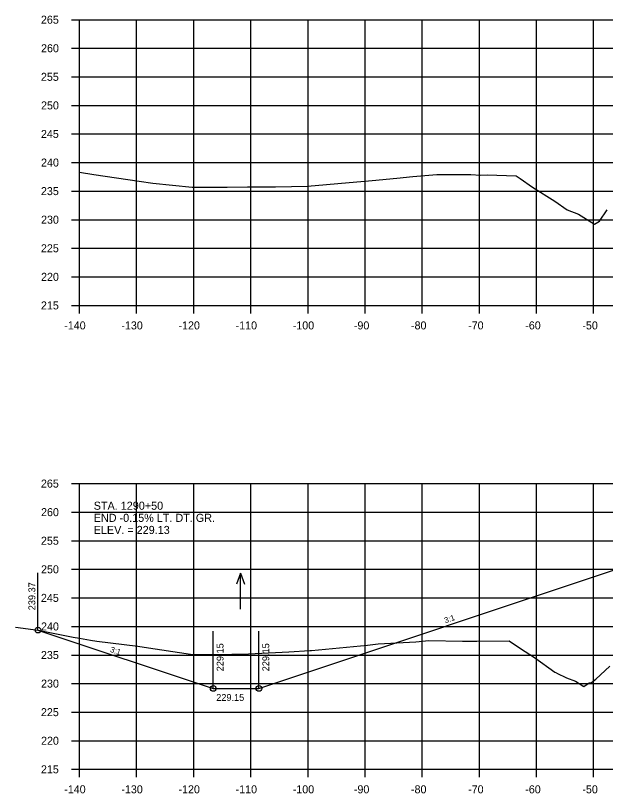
# Model space of a CAD drawing. Extents: x 1342547 to 1344156, y -1532351 to -1517216.
# Drawn here: x 1342551.7 to 1342654.9, y -1521241.8 to -1521105.7 of the extents above; entities that cross this region are included whole.
import ezdxf

# ---------------------------------------------------------------- set-up
doc = ezdxf.new("R2010")
doc.units = 0
for name, color, linetype in [('R_Axis', 7, 'Continuous'), ('R_Axis Annot', 7, 'Continuous'), ('R_Exist Surface', 7, 'Continuous'), ('R_Fin Surface', 7, 'Continuous'), ('R_Grid', 7, 'Continuous'), ('R_No Plot', 7, 'Continuous'), ('R_Water', 7, 'Continuous'), ('R_Water Annot', 7, 'Continuous'), ('R_Xsect Elev', 7, 'Continuous'), ('R_Xsect Slope', 7, 'Continuous')]:
    doc.layers.add(name, color=color, linetype=linetype)

msp = doc.modelspace()

# ---------------------------------------------------------------- linework, layer by layer
at = {"layer": 'R_Axis'}
for p, q in [((1342561.47, -1521106.39), (1342562.87, -1521106.39)), ((1342562.87, -1521156.39), (1342562.87, -1521106.39)), ((1342561.47, -1521111.39), (1342562.87, -1521111.39)), ((1342561.47, -1521116.39), (1342562.87, -1521116.39)), ((1342561.47, -1521121.39), (1342562.87, -1521121.39)), ((1342561.47, -1521126.39), (1342562.87, -1521126.39)), ((1342561.47, -1521131.39), (1342562.87, -1521131.39)), ((1342561.47, -1521136.39), (1342562.87, -1521136.39)), ((1342561.47, -1521141.39), (1342562.87, -1521141.39)), ((1342561.47, -1521146.39), (1342562.87, -1521146.39)), ((1342561.47, -1521151.39), (1342562.87, -1521151.39)), ((1342561.47, -1521156.39), (1342562.87, -1521156.39)), ((1342562.87, -1521156.39), (1342842.87, -1521156.39)), ((1342562.87, -1521157.79), (1342562.87, -1521156.39)), ((1342572.87, -1521157.79), (1342572.87, -1521156.39)), ((1342582.87, -1521157.79), (1342582.87, -1521156.39)), ((1342592.87, -1521157.79), (1342592.87, -1521156.39)), ((1342602.87, -1521157.79), (1342602.87, -1521156.39)), ((1342612.87, -1521157.79), (1342612.87, -1521156.39)), ((1342622.87, -1521157.79), (1342622.87, -1521156.39)), ((1342632.87, -1521157.79), (1342632.87, -1521156.39)), ((1342642.87, -1521157.79), (1342642.87, -1521156.39)), ((1342652.87, -1521157.79), (1342652.87, -1521156.39)), ((1342561.47, -1521187.57), (1342562.87, -1521187.57)), ((1342562.87, -1521237.57), (1342562.87, -1521187.57)), ((1342561.47, -1521192.57), (1342562.87, -1521192.57)), ((1342561.47, -1521197.57), (1342562.87, -1521197.57)), ((1342561.47, -1521202.57), (1342562.87, -1521202.57)), ((1342561.47, -1521207.57), (1342562.87, -1521207.57)), ((1342561.47, -1521212.57), (1342562.87, -1521212.57)), ((1342561.47, -1521217.57), (1342562.87, -1521217.57)), ((1342561.47, -1521222.57), (1342562.87, -1521222.57)), ((1342561.47, -1521227.57), (1342562.87, -1521227.57)), ((1342561.47, -1521232.57), (1342562.87, -1521232.57)), ((1342561.47, -1521237.57), (1342562.87, -1521237.57)), ((1342562.87, -1521237.57), (1342842.87, -1521237.57)), ((1342562.87, -1521238.97), (1342562.87, -1521237.57)), ((1342572.87, -1521238.97), (1342572.87, -1521237.57)), ((1342582.87, -1521238.97), (1342582.87, -1521237.57)), ((1342592.87, -1521238.97), (1342592.87, -1521237.57)), ((1342602.87, -1521238.97), (1342602.87, -1521237.57)), ((1342612.87, -1521238.97), (1342612.87, -1521237.57)), ((1342622.87, -1521238.97), (1342622.87, -1521237.57)), ((1342632.87, -1521238.97), (1342632.87, -1521237.57)), ((1342642.87, -1521238.97), (1342642.87, -1521237.57)), ((1342652.87, -1521238.97), (1342652.87, -1521237.57))]:
    msp.add_line(p, q, dxfattribs=at)
at = {"layer": 'R_Exist Surface'}
for points in [[(1342562.87, -1521133.05), (1342565.39, -1521133.51), (1342571.35, -1521134.33), (1342573.34, -1521134.67), (1342575.73, -1521134.97), (1342582.61, -1521135.67), (1342588.74, -1521135.68), (1342592.27, -1521135.65), (1342597.19, -1521135.64), (1342602.76, -1521135.53), (1342611.43, -1521134.77), (1342613.44, -1521134.59), (1342614.11, -1521134.53), (1342618.41, -1521134.1), (1342621.2, -1521133.81), (1342625.45, -1521133.49), (1342631.36, -1521133.51), (1342633.06, -1521133.58), (1342634.23, -1521133.56), (1342639.29, -1521133.71), (1342639.99, -1521134.19), (1342642.15, -1521135.69), (1342646.1, -1521138.15), (1342648.21, -1521139.68), (1342650.21, -1521140.42), (1342653.02, -1521142.2), (1342653.88, -1521141.63), (1342655.22, -1521139.64)], [(1342551.68, -1521212.67), (1342555.64, -1521213.2), (1342561.78, -1521214.42), (1342562.87, -1521214.62)], [(1342562.87, -1521214.62), (1342564.8, -1521214.98), (1342565.93, -1521215.14), (1342573.06, -1521216), (1342574.19, -1521216.19), (1342582.28, -1521217.4), (1342586.62, -1521217.47), (1342592.46, -1521217.39), (1342599.54, -1521216.99), (1342603.2, -1521216.78), (1342603.35, -1521216.78), (1342603.47, -1521216.77), (1342613.27, -1521215.82), (1342615.18, -1521215.64), (1342621.74, -1521215.25), (1342624.01, -1521215.01), (1342629.89, -1521215.16), (1342631.28, -1521215.15), (1342632.45, -1521215.17), (1342638.1, -1521215.1), (1342640.06, -1521216.43), (1342642.54, -1521218.03), (1342646.07, -1521220.55), (1342646.35, -1521220.7), (1342646.43, -1521220.77), (1342648.11, -1521221.54), (1342649.69, -1521222.12), (1342651.17, -1521223.07), (1342652.1, -1521222.45), (1342652.47, -1521222.4), (1342653.24, -1521221.79), (1342655.71, -1521219.52)]]:
    msp.add_lwpolyline(points, dxfattribs=at)
at = {"layer": 'R_Fin Surface'}
msp.add_lwpolyline([(1342555.6, -1521213.2), (1342586.28, -1521223.42), (1342594.28, -1521223.42), (1342659.86, -1521201.57), (1342659.87, -1521201.56), (1342671.37, -1521201.1), (1342673.37, -1521201.06), (1342702.87, -1521200.47), (1342732.37, -1521201.06), (1342734.37, -1521201.1), (1342745.87, -1521201.56), (1342745.88, -1521201.57), (1342750.14, -1521202.99), (1342753.33, -1521203.05)], dxfattribs=at)
at = {"layer": 'R_Grid'}
for p, q in [((1342562.87, -1521106.39), (1342842.87, -1521106.39)), ((1342562.87, -1521156.39), (1342562.87, -1521106.39)), ((1342572.87, -1521156.39), (1342572.87, -1521106.39)), ((1342582.87, -1521156.39), (1342582.87, -1521106.39)), ((1342592.87, -1521156.39), (1342592.87, -1521106.39)), ((1342602.87, -1521156.39), (1342602.87, -1521106.39)), ((1342612.87, -1521156.39), (1342612.87, -1521106.39)), ((1342622.87, -1521156.39), (1342622.87, -1521106.39)), ((1342632.87, -1521156.39), (1342632.87, -1521106.39)), ((1342642.87, -1521156.39), (1342642.87, -1521106.39)), ((1342652.87, -1521156.39), (1342652.87, -1521106.39)), ((1342562.87, -1521111.39), (1342842.87, -1521111.39)), ((1342562.87, -1521116.39), (1342842.87, -1521116.39)), ((1342562.87, -1521121.39), (1342842.87, -1521121.39)), ((1342562.87, -1521126.39), (1342842.87, -1521126.39)), ((1342562.87, -1521131.39), (1342842.87, -1521131.39)), ((1342562.87, -1521136.39), (1342842.87, -1521136.39)), ((1342562.87, -1521141.39), (1342842.87, -1521141.39)), ((1342562.87, -1521146.39), (1342842.87, -1521146.39)), ((1342562.87, -1521151.39), (1342842.87, -1521151.39)), ((1342562.87, -1521156.39), (1342842.87, -1521156.39)), ((1342562.87, -1521187.57), (1342842.87, -1521187.57)), ((1342562.87, -1521237.57), (1342562.87, -1521187.57)), ((1342572.87, -1521237.57), (1342572.87, -1521187.57)), ((1342582.87, -1521237.57), (1342582.87, -1521187.57)), ((1342592.87, -1521237.57), (1342592.87, -1521187.57)), ((1342602.87, -1521237.57), (1342602.87, -1521187.57)), ((1342612.87, -1521237.57), (1342612.87, -1521187.57)), ((1342622.87, -1521237.57), (1342622.87, -1521187.57)), ((1342632.87, -1521237.57), (1342632.87, -1521187.57)), ((1342642.87, -1521237.57), (1342642.87, -1521187.57)), ((1342652.87, -1521237.57), (1342652.87, -1521187.57)), ((1342562.87, -1521192.57), (1342842.87, -1521192.57)), ((1342562.87, -1521197.57), (1342842.87, -1521197.57)), ((1342562.87, -1521202.57), (1342842.87, -1521202.57)), ((1342562.87, -1521207.57), (1342842.87, -1521207.57)), ((1342562.87, -1521212.57), (1342842.87, -1521212.57)), ((1342562.87, -1521217.57), (1342842.87, -1521217.57)), ((1342562.87, -1521222.57), (1342842.87, -1521222.57)), ((1342562.87, -1521227.57), (1342842.87, -1521227.57)), ((1342562.87, -1521232.57), (1342842.87, -1521232.57)), ((1342562.87, -1521237.57), (1342842.87, -1521237.57))]:
    msp.add_line(p, q, dxfattribs=at)
at = {"layer": 'R_No Plot'}
for centre in [(1342555.6, -1521213.2), (1342586.28, -1521223.42), (1342594.28, -1521223.42)]:
    msp.add_circle(centre, 0.5, dxfattribs=at)
at = {"layer": 'R_Water'}
for p, q in [((1342591.04, -1521203.27), (1342590.34, -1521205.19)), ((1342591.04, -1521209.55), (1342591.04, -1521203.27)), ((1342591.04, -1521203.27), (1342591.74, -1521205.19))]:
    msp.add_line(p, q, dxfattribs=at)
at = {"layer": 'R_Xsect Elev'}
for p, q in [((1342555.6, -1521213.2), (1342555.6, -1521203.2)), ((1342586.28, -1521223.42), (1342586.28, -1521213.42)), ((1342594.28, -1521223.42), (1342594.28, -1521213.42))]:
    msp.add_line(p, q, dxfattribs=at)

# ---------------------------------------------------------------- texts
at = {"layer": 'R_Axis Annot'}
for s, p in [('265', (1342556.12, -1521107.09)), ('260', (1342556.14, -1521112.09)), ('255', (1342556.12, -1521117.09)), ('250', (1342556.14, -1521122.09)), ('245', (1342556.12, -1521127.09)), ('240', (1342556.14, -1521132.09)), ('235', (1342556.12, -1521137.09)), ('230', (1342556.14, -1521142.09)), ('225', (1342556.12, -1521147.09)), ('220', (1342556.14, -1521152.09)), ('215', (1342556.12, -1521157.09)), ('-140', (1342560.2, -1521160.59)), ('-130', (1342570.2, -1521160.59)), ('-120', (1342580.2, -1521160.59)), ('-110', (1342590.2, -1521160.59)), ('-100', (1342600.2, -1521160.59)), ('-90', (1342610.9, -1521160.59)), ('-80', (1342620.9, -1521160.59)), ('-70', (1342630.9, -1521160.59)), ('-60', (1342640.9, -1521160.59)), ('-50', (1342650.9, -1521160.59)), ('265', (1342556.12, -1521188.27)), ('260', (1342556.14, -1521193.27)), ('255', (1342556.12, -1521198.27)), ('250', (1342556.14, -1521203.27)), ('245', (1342556.12, -1521208.27)), ('240', (1342556.14, -1521213.27)), ('235', (1342556.12, -1521218.27)), ('230', (1342556.14, -1521223.27)), ('225', (1342556.12, -1521228.27)), ('220', (1342556.14, -1521233.27)), ('215', (1342556.12, -1521238.27)), ('-140', (1342560.2, -1521241.77)), ('-130', (1342570.2, -1521241.77)), ('-120', (1342580.2, -1521241.77)), ('-110', (1342590.2, -1521241.77)), ('-100', (1342600.2, -1521241.77)), ('-90', (1342610.9, -1521241.77)), ('-80', (1342620.9, -1521241.77)), ('-70', (1342630.9, -1521241.77)), ('-60', (1342640.9, -1521241.77)), ('-50', (1342650.9, -1521241.77))]:
    msp.add_text(s, height=1.4, dxfattribs=at).set_placement(p)
at = {"layer": 'R_Water Annot'}
for s, height, p in [('STA. 1290+50', 1.4147, (1342565.36, -1521192.15)), ('END -0.15% LT. DT. GR.', 1.4147, (1342565.36, -1521194.27)), ('ELEV. = 229.13', 1.4147, (1342565.36, -1521196.39)), ('229.15', 1.2, (1342586.8, -1521225.6)), ('229.15', 1.2, (1342586.8, -1521225.6))]:
    msp.add_text(s, height=height, dxfattribs=at).set_placement(p)
at = {"layer": 'R_Xsect Elev'}
for s, p in [('239.37', (1342555.13, -1521209.74)), ('229.15', (1342588.08, -1521220.42)), ('229.15', (1342596.08, -1521220.42))]:
    msp.add_text(s, height=1.2, rotation=90, dxfattribs=at).set_placement(p)
at = {"layer": 'R_Xsect Slope'}
for rotation, p in [(18.4349, (1342626.91, -1521212.02)), (341.5651, (1342568.15, -1521217.01))]:
    msp.add_text('3:1', height=1, rotation=rotation, dxfattribs=at).set_placement(p)

doc.saveas('drawing.dxf')
